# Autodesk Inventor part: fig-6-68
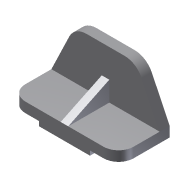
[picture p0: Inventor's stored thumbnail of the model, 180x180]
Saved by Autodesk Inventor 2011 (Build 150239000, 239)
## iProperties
Shininess: 77.0
Length Units: 11269
Angle Units: 11279
Time Units: 11290
Mass Units: 11283
Length Display Precision: 3
Angle Display Precision: 2
Created: 2001-12
Part Number: fig-6-68
Document SubType Name: Modeling
Designer: Renu Muthoo
Density: 1 g/cm^3
Density: 0.0
Volumn: 0.0
Area: 0.0
PropertySet Name: Model Information
Control State: 0
Master: False
Checked Out: False
Author: Renu Muthoo
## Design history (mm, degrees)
node "Sketch1"
sketch "Sketch2"
  geometry: L1 (-67.219, 19.116)-(148.781, 19.116); L2 (148.781, 19.116)-(148.781, -0.884); L3 (-67.219, -0.884)-(-67.219, 19.116); L4 (-10.219, -0.884)-(-10.219, -9.884); L5 (-10.219, -9.884)-(91.781, -9.884); L6 (91.781, -9.884)-(91.781, -0.884); L7 (148.781, -0.884)-(91.781, -0.884); L8 (-10.219, -0.884)-(-67.219, -0.884)
  constraints: 16 end point, 5 parallel, 4 perpendicular, 2 equal length, 1 horizontal
  dimensions: "d0" = 102 distance of L4.end L5.end; "d1" = 57 distance of L4.start L3.start; "d2" = 29 distance between parallel lines of L1 L5; "d3" = 20 distance of L1.end L2.end
extrude "Extrusion1" new body sketch "Sketch2" distance "d4" = 102; taper "d5" = 0 deg
sketch "Sketch3"
  geometry: L1 (67.219, -19.116)-(-148.781, -19.116) reference; L2 (67.219, -19.116)-(31.475, -93.564); L3 (-2.781, -115.116)-(-78.781, -115.116); L4 (-113.038, -93.564)-(-148.781, -19.116); A1 r 38 centre (-2.781, -77.116) between (-2.781, -115.116) and (31.475, -93.564); A2 r 38 centre (-78.781, -77.116) between (-113.038, -93.564) and (-78.781, -115.116)
  constraints: 6 end point, 4 point on circle, 4 tangent, 2 centre point, 1 equal length, 1 equal radius, 1 parallel
  dimensions: "d6" = 96 distance between parallel lines of L3 L1; "d7" = 38 radius of A1; "d8" = 76 distance of A2.centre A1.centre
extrude "Extrusion2" join sketch "Sketch3" distance "d9" = 20; taper "d10" = 0 deg
fillet "Fillet1" dims "d11" = 30
workplane "Work Plane1"
sketch "Sketch7"
  geometry: L1 (0, -82)-(-39.557, 0)
  constraints: 2 end point
feature "Rib4" sketch "Sketch7" dims "d37" = 1, "d38" = 15, "d39" = 0
body "Solid1"
other parameters: "d12" = -108
